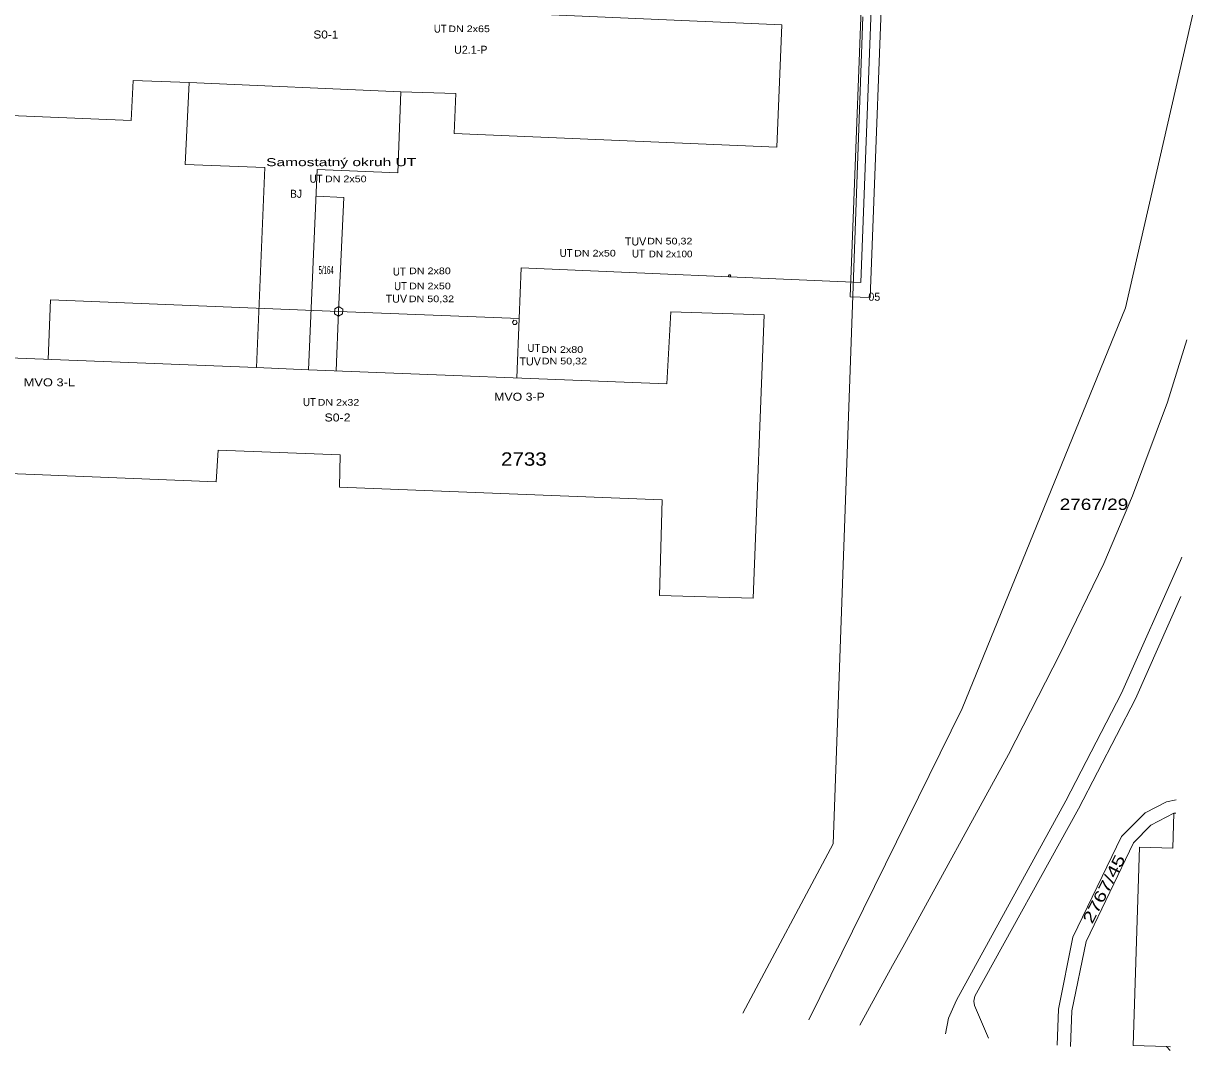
# Model space of a CAD drawing. Extents: x -725191 to -724881, y -978080 to -977718.
# Drawn here: x -725060.2 to -724884.7, y -978080.3 to -977926.4 of the extents above; entities that cross this region are included whole.
import ezdxf
from ezdxf.enums import TextEntityAlignment as Align

# ---------------------------------------------------------------- set-up
doc = ezdxf.new("R2010")
doc.units = 0
doc.header["$LTSCALE"] = 0.48
for name, color, linetype, lineweight in [('1', 7, 'Continuous', 13), ('4', 7, 'Continuous', 13), ('46', 7, 'Continuous', 13), ('63', 7, 'Continuous', 13), ('7', 7, 'Continuous', 13)]:
    doc.layers.add(name, color=color, linetype=linetype, lineweight=lineweight)
doc.layers.add('2', color=7, linetype='Continuous')
doc.layers.add('20', color=7, linetype='Continuous')

msp = doc.modelspace()

# ---------------------------------------------------------------- linework, layer by layer
at = {"layer": '1'}
for p, q in [((-724884.666, -977923.907), (-724895, -977969)), ((-724938.86, -978049.3), (-724934.4, -977925.39)), ((-724895, -977969), (-724919.5, -978029)), ((-724949.19, -977970.06), (-724963.19, -977969.6)), ((-724942.465, -978075.673), (-724919.5, -978029)), ((-724912.56, -978035.9), (-724928.41, -978064.77)), ((-724952.381, -978074.663), (-724938.86, -978049.3)), ((-724928.41, -978064.77), (-724929.92, -978067.51)), ((-724929.92, -978067.51), (-724934.841, -978076.45)), ((-724888.86, -978079.67), (-724888.286, -978079.69))]:
    msp.add_line(p, q, dxfattribs=at)
for points in [[(-725035.36, -977935.22), (-725043.75, -977934.93), (-725044.06, -977940.9), (-725092.45, -977938.91), (-725091.57, -977920.38), (-725042.12, -977922.44)], [(-724996.03, -977924.46), (-724946.52, -977926.6), (-724947.3, -977944.91), (-724995.66, -977942.85)], [(-725035.36, -977935.22), (-725035.96, -977947.51), (-725024.02, -977947.97), (-725025.29, -977977.93)], [(-725017.49, -977978.26), (-725016.18, -977948.26), (-725004.1, -977948.75), (-725003.66, -977936.63)], [(-724995.66, -977942.85), (-724995.42, -977936.9), (-725003.66, -977936.63)], [(-725025.29, -977977.93), (-725078.99, -977975.81), (-725078.53, -977964.87), (-725092.54, -977964.35)], [(-724963.19, -977969.6), (-724963.75, -977980.36), (-725017.49, -977978.26)], [(-724949.19, -977970.06), (-724950.85, -978012.5), (-724964.86, -978012.07), (-724964.45, -977997.73), (-725012.84, -977995.88)], [(-724885.825, -977973.783), (-724888.72, -977983.12), (-724893.96, -977997.17), (-724898.28, -978007.28)], [(-725079.76, -977993.09), (-725031.32, -977995.08), (-725031.04, -977990.3), (-725012.72, -977991), (-725012.84, -977995.88)], [(-724898.28, -978007.28), (-724904.79, -978020.77), (-724912.56, -978035.9)], [(-724902.08, -978044.03), (-724893.53, -978027.58), (-724886.719, -978012.223)], [(-724887.427, -978042.714), (-724888.88, -978043), (-724892.08, -978044.64), (-724895.6, -978048.18)], [(-724915.566, -978078.414), (-724917.67, -978073.53), (-724917.77, -978072.84), (-724917.62, -978072.09), (-724902.08, -978044.03)], [(-724893.81, -978049.15), (-724891.2, -978046.52), (-724887.77, -978044.68)], [(-724892.94, -978049.81), (-724887.93, -978049.96), (-724887.77, -978044.68), (-724887.473, -978044.689)], [(-724895.6, -978048.18), (-724902.91, -978063.29), (-724905.07, -978074.05), (-724905.256, -978079.465)], [(-724903.251, -978079.669), (-724903.08, -978074.32), (-724900.94, -978063.93), (-724893.81, -978049.15)], [(-724888.3, -978080.265), (-724888.86, -978079.67), (-724893.85, -978079.51), (-724892.94, -978049.81)]]:
    msp.add_lwpolyline(points, dxfattribs=at)
at = {"layer": '4'}
for p, q in [((-725003.66, -977936.63), (-725035.36, -977935.22)), ((-725025.29, -977977.93), (-725017.49, -977978.26))]:
    msp.add_line(p, q, dxfattribs=at)
for points in [[(-724886.582, -978006.331), (-724886.76, -978006.84), (-724895.62, -978026.74), (-724903.97, -978042.86)], [(-724903.97, -978042.86), (-724920.35, -978072.73), (-724921.53, -978075.41), (-724922.015, -978077.757)]]:
    msp.add_lwpolyline(points, dxfattribs=at)
at = {"layer": '46'}
msp.add_lwpolyline([(-724954.272, -977964.06), (-724954.19, -977964.215), (-724954.288, -977964.36), (-724954.468, -977964.35), (-724954.549, -977964.196), (-724954.452, -977964.051)], close=True, dxfattribs=at)
at = {"layer": '63'}
msp.add_line((-724985.885, -977970.588), (-724986.233, -977979.481), dxfattribs=at)
for points in [[(-724946.744, -977810.509), (-724949.211, -977812.215), (-724940.029, -977825.495), (-724942.001, -977873.733), (-724942.701, -977873.705), (-724942.819, -977876.703), (-724942.12, -977876.73), (-724943.226, -977905.12), (-724943.926, -977905.093), (-724944.039, -977908.091), (-724934.046, -977908.468), (-724936.266, -977967.326), (-724933.268, -977967.439), (-724931.048, -977908.581), (-724930.349, -977908.607), (-724930.236, -977905.61), (-724940.229, -977905.233), (-724938.908, -977876.858), (-724932.627, -977877.107), (-724932.509, -977874.109), (-724938.79, -977873.86), (-724936.993, -977824.611)], [(-724946.744, -977810.509), (-724949.211, -977812.215), (-724940.029, -977825.495), (-724942.001, -977873.733), (-724942.701, -977873.705), (-724942.819, -977876.703), (-724942.12, -977876.73), (-724943.226, -977905.12), (-724943.926, -977905.093), (-724944.039, -977908.091), (-724934.046, -977908.468), (-724936.266, -977967.326), (-724933.268, -977967.439), (-724931.048, -977908.581), (-724930.349, -977908.607), (-724930.236, -977905.61), (-724940.229, -977905.233), (-724938.908, -977876.858), (-724932.627, -977877.107), (-724932.509, -977874.109), (-724938.79, -977873.86), (-724936.993, -977824.611)], [(-724946.744, -977810.509), (-724949.211, -977812.215), (-724940.029, -977825.495), (-724942.001, -977873.733), (-724942.701, -977873.705), (-724942.819, -977876.703), (-724942.12, -977876.73), (-724943.226, -977905.12), (-724943.926, -977905.093), (-724944.039, -977908.091), (-724934.046, -977908.468), (-724936.266, -977967.326), (-724933.268, -977967.439), (-724931.048, -977908.581), (-724930.349, -977908.607), (-724930.236, -977905.61), (-724940.229, -977905.233), (-724938.908, -977876.858), (-724932.627, -977877.107), (-724932.509, -977874.109), (-724938.79, -977873.86), (-724936.993, -977824.611)], [(-725013.553, -977969.151), (-725012.942, -977968.81), (-725012.354, -977969.189), (-725012.376, -977969.909), (-725012.988, -977970.25), (-725013.576, -977969.871)], [(-724986.719, -977970.85), (-724986.369, -977970.87), (-724986.222, -977971.188), (-724986.425, -977971.485), (-724986.774, -977971.466), (-724986.921, -977971.148)]]:
    msp.add_lwpolyline(points, close=True, dxfattribs=at)
for points in [[(-724946.744, -977810.509), (-724949.211, -977812.215), (-724940.029, -977825.495), (-724942.001, -977873.733), (-724942.701, -977873.705), (-724942.819, -977876.703), (-724942.12, -977876.73), (-724943.226, -977905.12), (-724943.926, -977905.093), (-724944.039, -977908.091), (-724943.34, -977908.117), (-724934.046, -977908.468), (-724936.266, -977967.326), (-724933.268, -977967.439), (-724931.048, -977908.581), (-724930.349, -977908.607), (-724930.236, -977905.61), (-724930.935, -977905.583), (-724933.933, -977905.47)], [(-724939.636, -977839.037), (-724940.981, -977875.775), (-724940.582, -977875.791), (-724940.821, -977881.133), (-724941.626, -977902.478), (-724941.784, -977906.675), (-724932.491, -977907.026), (-724934.684, -977965.184)], [(-725016.355, -977952.256), (-725012.178, -977952.439), (-725012.965, -977969.53)], [(-725056.508, -977976.705), (-725056.154, -977967.812), (-725012.965, -977969.53), (-724985.885, -977970.588), (-724985.589, -977962.994), (-724934.684, -977965.184)], [(-724985.885, -977970.588), (-724985.589, -977962.994), (-724934.684, -977965.184)], [(-725013.312, -977978.423), (-725012.965, -977969.53), (-724985.885, -977970.588), (-724986.233, -977979.481)]]:
    msp.add_lwpolyline(points, dxfattribs=at)

# ---------------------------------------------------------------- texts
at = {"layer": '2', "width": 1.25}
msp.add_text('2767/29', height=1.7, dxfattribs=at).set_placement((-724904.883, -977999.27))
at = {"layer": '2', "width": 1.35}
msp.add_text('2767/45', height=1.7, rotation=63.025, dxfattribs=at).set_placement((-724900.012, -978061.388))
at = {"layer": '20', "width": 1.15}
msp.add_text('2733', height=2, dxfattribs=at).set_placement((-724985.2, -977992.64), align=Align.CENTER)
at = {"layer": '63'}
for s, width, p in [('DN 2x65', 1.2, (-724993.4055, -977927.684)), ('DN 2x50', 1.2, (-725011.8925, -977950.169)), ('DN 50,32', 1.2, (-724963.326, -977959.494)), ('DN 2x50', 1.2, (-724974.5435, -977961.298)), ('DN 2x100', 1.1, (-724963.201, -977961.419)), ('DN 2x80', 1.2, (-724999.278, -977963.948)), ('DN 2x50', 1.2, (-724999.278, -977966.211)), ('DN 50,32', 1.2, (-724999.046, -977968.142)), ('DN 2x80', 1.2, (-724979.4315, -977975.737)), ('DN 50,32', 1.2, (-724979.118, -977977.466)), ('DN 2x32', 1.2, (-725012.99, -977983.651))]:
    msp.add_text(s, height=1, dxfattribs=dict(at, width=width)).set_placement(p, align=Align.CENTER)
at = {"layer": '7'}
for s, width, p in [('UT', 0.9, (-724997.7295, -977927.759)), ('S0-1', 1.1, (-725014.884, -977928.639)), ('Samostatný okruh UT', 1.45, (-725012.582, -977947.762)), ('UT', 0.9, (-725016.3415, -977950.244)), ('BJ', 0.95, (-725019.35, -977952.5)), ('UT', 0.9, (-724978.8675, -977961.374)), ('UT', 0.9, (-724968.0255, -977961.449)), ('5/164', 0.45, (-725014.838, -977963.93)), ('UT', 0.9, (-725003.8715, -977964.156)), ('UT', 0.9, (-725003.6835, -977966.337)), ('UT', 0.9, (-724983.6925, -977975.586)), ('MVO 3-L', 1.2, (-725056.329, -977980.749)), ('UT', 0.9, (-725017.3445, -977983.708)), ('MVO 3-P', 1.15, (-724985.859, -977982.909)), ('S0-2', 1.15, (-725013.1295, -977986.014))]:
    msp.add_text(s, height=1.2, dxfattribs=dict(at, width=width)).set_placement(p, align=Align.CENTER)
for s, p in [('U2.1-P', (-724993.155, -977930.918)), ('TUV', (-724968.4645, -977959.644)), ('TUV', (-725004.31, -977968.217)), ('05', (-724932.6695, -977967.924)), ('TUV', (-724984.2565, -977977.617))]:
    msp.add_text(s, height=1.2, dxfattribs=at).set_placement(p, align=Align.CENTER)

doc.saveas('drawing.dxf')
